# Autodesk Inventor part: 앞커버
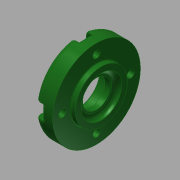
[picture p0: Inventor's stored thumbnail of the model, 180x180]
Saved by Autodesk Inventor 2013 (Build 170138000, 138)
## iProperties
Created: 2015-11
Part Number: 앞커버
Material: 알루미늄 6061
Document SubType Name: Modeling
Designer: mduedu
Density: 1 g/cm^3
Author: mduedu
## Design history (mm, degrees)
sketch "스케치1"
  geometry: L1 (-7, 0)-(7, 0); L2 (-7, 0)-(-7, 27); L3 (-7, 27)-(4, 27); L4 (4, 27)-(4, 16); L5 (4, 16)-(7, 16); L6 (7, 16)-(7, 0); 2 further points
  constraints: 12 end point, 3 perpendicular, 2 parallel, 1 coincident, 1 horizontal, 1 midpoint
  dimensions: "d0" = 14 distance of L1.start L1.end; "d1" = 54 diameter of L3 L1; "d2" = 3 distance of L4.end L5.end; "d3" = 32 diameter of L5 L1
revolve "회전1" sketch "스케치1" stored, may be unused: angle "d4" = 90 deg
hole "구멍1" diameter "d7" = 25; stored, may be unused: countersink angle "d11" = 90 deg, drill point angle "d13" = 0 deg; dims "d5" = 10, "d6" = 10, "d8" = 6, "d9" = 4, "d10" = 2, "d12" = 3
hole "구멍2" diameter "d16" = 25; stored, may be unused: countersink angle "d20" = 90 deg, drill point angle "d22" = 0 deg; dims "d17" = 6, "d18" = 4, "d19" = 2, "d21" = 7.7, "d58" = 10, "d59" = 10
hole "구멍3" diameter "d25" = 17; stored, may be unused: countersink angle "d29" = 90 deg, drill point angle "d31" = 0 deg; dims "d23" = 10, "d24" = 10, "d26" = 6, "d27" = 4, "d28" = 2, "d30" = 4.2
chamfer "모따기1" distance "d32" = 0.6; stored, may be unused: second distance "d33" = 2, angle "d34" = 30 deg
fillet "모깎기1" dims "d35" = 0.3
fillet "모깎기2" dims "d36" = 3
fillet "모깎기3" dims "d37" = 3
fillet "모깎기4" dims "d38" = 0.3
sketch "스케치3" dims "d61" = 42
  geometry: C1 r 27 at (0, 0) reference; 2 further points
  constraints: 2 vertical alignment, 1 coincident, 2 other
hole "구멍4" sketch "스케치3" at (0, 21) diameter "d44" = 4.5; stored, may be unused: countersink angle "d48" = 90 deg, drill point angle "d50" = 0 deg; dims "d45" = 6, "d46" = 8, "d47" = 4.6, "d49" = 8
sketch "스케치4"
  geometry: L1 (-4, 5.702)-(-4, 0); L2 (4, 5.702)-(4, 0); A1 r 27 centre (0, -21) between (-4, 5.702) and (4, 5.702) reference; A2 r 4 centre (0, 0) between (-2.824, 2.833) and (2.824, 2.833) reference
  constraints: 4 end point, 4 point on circle, 2 tangent, 2 vertical
extrude "돌출1" cut sketch "스케치4" stored distance "d51" = 0; taper "d52" = 0 deg
fillet "모깎기5" dims "d56" = 0.3
fillet "모깎기6" dims "d57" = 1
node "솔리드1"
pattern_circular "원형 패턴2" dims angle "d64" = 360 deg
pattern_circular "원형 패턴1" dims angle "d54" = 360 deg
